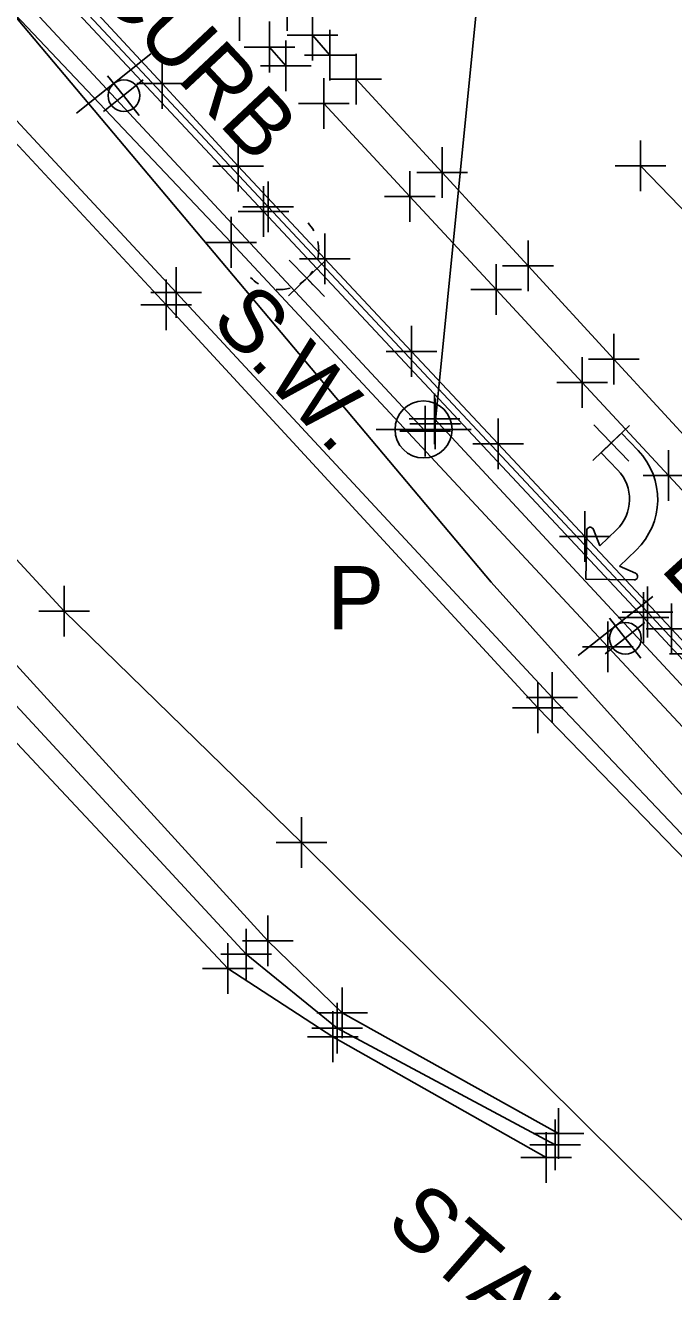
# Model space of a CAD drawing. Extents: x 0 to 1944463, y 0 to 420651.
# Drawn here: x 1943264.8 to 1943315.9, y 417235.5 to 417335.4 of the extents above; entities that cross this region are included whole.
import ezdxf

# ---------------------------------------------------------------- set-up
doc = ezdxf.new("R2010")
doc.units = 0
for name, color, linetype in [('SUR - DRG - Pipes and Culverts', 7, 'Continuous'), ('SUR - DRG - Pipes and Culverts - Points - Locators', 7, 'Continuous'), ('SUR - DTM - Breaklines', 7, 'Continuous'), ('SUR - DTM - Breaklines - Points - Locators', 7, 'Continuous'), ('SUR - NON-TRAN - Features Text', 7, 'Continuous'), ('SUR - TR-CTRL - Pavement Marking', 7, 'Continuous'), ('SUR - TR-CTRL - Pavement Marking - Points - Locators', 7, 'Continuous'), ('SUR - TR-CTRL - Signs and Devices', 7, 'Continuous'), ('SUR - TR-CTRL - Signs and Devices - Points - Locators', 7, 'Continuous'), ('SUR - TRAN - Features', 7, 'Continuous'), ('SUR - TRAN - Features - Points - Locators', 7, 'Continuous'), ('SUR - TRAN - Features Text', 7, 'Continuous'), ('SUR - UTL - Fiber Optic Cable (Underground)', 7, 'Continuous'), ('SUR - UTL - Overhead Wire Crossings', 7, 'Continuous'), ('SUR - UTL - Overhead Wire Crossings - Points - Locators', 7, 'Continuous'), ('SUR - UTL - Poles and Miscellaneous', 7, 'Continuous'), ('SUR - UTL - Poles and Miscellaneous - Points - Locators', 7, 'Continuous'), ('SUR - UTL - Poles and Miscellaneous Text', 7, 'Continuous')]:
    doc.layers.add(name, color=color, linetype=linetype)

msp = doc.modelspace()

# ---------------------------------------------------------------- linework, layer by layer
at = {"layer": 'SUR - DRG - Pipes and Culverts'}
for points in [[(1943306.855, 417247.978), (1943289.784, 417257.5), (1943283.915, 417263.16), (1943254.781, 417295.058), (1943224.294, 417329.482), (1943197.051, 417363.643)], [(1943305.862, 417246.088), (1943289.035, 417255.612), (1943280.758, 417260.995), (1943252.088, 417291.545), (1943220.601, 417326.41), (1943196.115, 417357.405)]]:
    msp.add_lwpolyline(points, dxfattribs=at)
at = {"layer": 'SUR - DRG - Pipes and Culverts - Points - Locators'}
for p, q in [((1943283.915, 417263.16), (1943283.915, 417265.16)), ((1943283.915, 417263.16), (1943281.915, 417263.16)), ((1943283.915, 417263.16), (1943285.915, 417263.16)), ((1943283.915, 417263.16), (1943283.915, 417261.16)), ((1943280.758, 417260.995), (1943280.758, 417262.995)), ((1943280.758, 417260.995), (1943278.758, 417260.995)), ((1943280.758, 417260.995), (1943282.758, 417260.995)), ((1943280.758, 417260.995), (1943280.758, 417258.995)), ((1943289.784, 417257.5), (1943289.784, 417259.5)), ((1943289.784, 417257.5), (1943287.784, 417257.5)), ((1943289.035, 417255.612), (1943289.035, 417257.612)), ((1943289.784, 417257.5), (1943291.784, 417257.5)), ((1943289.784, 417257.5), (1943289.784, 417255.5)), ((1943289.035, 417255.612), (1943287.035, 417255.612)), ((1943289.035, 417255.612), (1943291.035, 417255.612)), ((1943289.035, 417255.612), (1943289.035, 417253.612)), ((1943306.855, 417247.978), (1943306.855, 417249.978)), ((1943305.862, 417246.088), (1943305.862, 417248.088)), ((1943306.855, 417247.978), (1943304.855, 417247.978)), ((1943306.855, 417247.978), (1943308.855, 417247.978)), ((1943306.855, 417247.978), (1943306.855, 417245.978)), ((1943305.862, 417246.088), (1943303.862, 417246.088)), ((1943305.862, 417246.088), (1943307.862, 417246.088)), ((1943305.862, 417246.088), (1943305.862, 417244.088))]:
    msp.add_line(p, q, dxfattribs=at)
at = {"layer": 'SUR - DTM - Breaklines'}
for points in [[(1943201.925, 417419.272), (1943219.399, 417398.292), (1943235.519, 417375.7), (1943243.356, 417364.884), (1943258.929, 417346.985), (1943283.566, 417320.678), (1943313.562, 417288.656), (1943327.29, 417273.893), (1943334.736, 417264.52), (1943341.659, 417251.305), (1943344.574, 417242.404)], [(1943198.046, 417414.134), (1943214.079, 417390.624), (1943227.284, 417369.761), (1943234.656, 417359.391), (1943251.574, 417339.468), (1943275.895, 417313.326), (1943305.21, 417281.554), (1943319.493, 417266.816), (1943326.151, 417258.389), (1943333.033, 417247.541), (1943335.935, 417239.942), (1943336.414, 417217.406)], [(1943306.58, 417247.082), (1943289.389, 417256.286), (1943282.191, 417262.111), (1943253.295, 417293.316), (1943222.689, 417327.178), (1943196.285, 417361.224)], [(1943302.769, 417192.969), (1943316.957, 417194.129), (1943325.403, 417222.632), (1943318.173, 417239.593), (1943286.555, 417270.931), (1943267.833, 417289.169), (1943243.263, 417315.732), (1943226.41, 417332.649)]]:
    msp.add_lwpolyline(points, dxfattribs=at)
at = {"layer": 'SUR - DTM - Breaklines - Points - Locators'}
for p, q in [((1943283.566, 417320.678), (1943283.566, 417322.678)), ((1943283.566, 417320.678), (1943281.566, 417320.678)), ((1943283.566, 417320.678), (1943285.566, 417320.678)), ((1943283.566, 417320.678), (1943283.566, 417318.678)), ((1943275.895, 417313.326), (1943275.895, 417315.326)), ((1943275.895, 417313.326), (1943273.895, 417313.326)), ((1943275.895, 417313.326), (1943277.895, 417313.326)), ((1943275.895, 417313.326), (1943275.895, 417311.326)), ((1943267.833, 417289.169), (1943267.833, 417291.169)), ((1943313.562, 417288.656), (1943313.562, 417290.656)), ((1943267.833, 417289.169), (1943265.833, 417289.169)), ((1943267.833, 417289.169), (1943269.833, 417289.169)), ((1943267.833, 417289.169), (1943267.833, 417287.169)), ((1943313.562, 417288.656), (1943311.562, 417288.656)), ((1943313.562, 417288.656), (1943315.562, 417288.656)), ((1943313.562, 417288.656), (1943313.562, 417286.656)), ((1943305.21, 417281.554), (1943305.21, 417283.554)), ((1943305.21, 417281.554), (1943303.21, 417281.554)), ((1943305.21, 417281.554), (1943307.21, 417281.554)), ((1943305.21, 417281.554), (1943305.21, 417279.554)), ((1943286.555, 417270.931), (1943286.555, 417272.931)), ((1943286.555, 417270.931), (1943284.555, 417270.931)), ((1943286.555, 417270.931), (1943288.555, 417270.931)), ((1943286.555, 417270.931), (1943286.555, 417268.931)), ((1943282.191, 417262.111), (1943282.191, 417264.111)), ((1943282.191, 417262.111), (1943280.191, 417262.111)), ((1943282.191, 417262.111), (1943284.191, 417262.111)), ((1943282.191, 417262.111), (1943282.191, 417260.111)), ((1943289.389, 417256.286), (1943289.389, 417258.286)), ((1943289.389, 417256.286), (1943287.389, 417256.286)), ((1943289.389, 417256.286), (1943291.389, 417256.286)), ((1943289.389, 417256.286), (1943289.389, 417254.286)), ((1943306.58, 417247.082), (1943306.58, 417249.082)), ((1943306.58, 417247.082), (1943304.58, 417247.082)), ((1943306.58, 417247.082), (1943308.58, 417247.082)), ((1943306.58, 417247.082), (1943306.58, 417245.082))]:
    msp.add_line(p, q, dxfattribs=at)
at = {"layer": 'SUR - TR-CTRL - Pavement Marking'}
for p, q in [((1943310.207, 417301.657), (1943311.809, 417303.198)), ((1943310.207, 417301.657), (1943311.809, 417303.198)), ((1943311.809, 417303.198), (1943313.121, 417301.834)), ((1943311.809, 417303.198), (1943313.121, 417301.834)), ((1943311.008, 417302.427), (1943311.008, 417302.427)), ((1943310.207, 417301.657), (1943311.519, 417300.293)), ((1943310.207, 417301.657), (1943311.519, 417300.293)), ((1943308.995, 417291.698), (1943309.069, 417295.511)), ((1943308.995, 417291.698), (1943309.069, 417295.511)), ((1943310.112, 417294.314), (1943309.605, 417295.606)), ((1943310.112, 417294.314), (1943309.605, 417295.606)), ((1943311.428, 417295.58), (1943310.112, 417294.314)), ((1943311.428, 417295.58), (1943310.112, 417294.314)), ((1943312.969, 417293.978), (1943311.652, 417292.712)), ((1943312.969, 417293.978), (1943311.652, 417292.712)), ((1943311.652, 417292.712), (1943312.925, 417292.156)), ((1943311.652, 417292.712), (1943312.925, 417292.156)), ((1943308.995, 417291.698), (1943312.808, 417291.624)), ((1943308.995, 417291.698), (1943312.808, 417291.624))]:
    msp.add_line(p, q, dxfattribs=at)
for points in [[(1943268.798, 417338.12), (1943275.572, 417330.765), (1943281.577, 417324.245), (1943288.415, 417316.949), (1943295.254, 417309.653), (1943302.092, 417302.356), (1943308.93, 417295.06), (1943315.768, 417287.763), (1943317.602, 417285.807), (1943324.319, 417278.398), (1943331.036, 417270.99), (1943333.702, 417268.05), (1943337.073, 417264.332), (1943339.809, 417260.214)], [(1943287.426, 417334.58), (1943288.807, 417333.008)], [(1943284.029, 417333.651), (1943285.324, 417332.164)], [(1943290.889, 417331.107), (1943297.664, 417323.752), (1943304.439, 417316.397), (1943311.214, 417309.042), (1943317.989, 417301.686), (1943320.289, 417299.189), (1943327.064, 417291.834), (1943333.839, 417284.479), (1943340.614, 417277.123), (1943347.389, 417269.768), (1943354.164, 417262.413), (1943358.443, 417257.768)], [(1943313.304, 417324.282), (1943320.265, 417317.103), (1943320.521, 417316.838)]]:
    msp.add_lwpolyline(points, dxfattribs=at)
for centre, radius, start, end in [((1943309.117, 417297.982), 5.556, 313.89003, 43.89003), ((1943309.117, 417297.982), 5.556, 313.89003, 43.89003), ((1943309.117, 417297.982), 3.333, 313.89003, 43.89003), ((1943309.117, 417297.982), 3.333, 313.89003, 43.89003), ((1943309.347, 417295.505), 0.278, 21.39686, 178.89003), ((1943309.347, 417295.505), 0.278, 21.39686, 178.89003), ((1943312.814, 417291.902), 0.278, 268.89003, 66.33829), ((1943312.814, 417291.902), 0.278, 268.89003, 66.33829)]:
    msp.add_arc(centre, radius, start, end, dxfattribs=at)
at = {"layer": 'SUR - TR-CTRL - Pavement Marking - Points - Locators'}
for p, q in [((1943281.667, 417336.128), (1943281.667, 417334.128)), ((1943285.426, 417336.915), (1943285.426, 417334.915)), ((1943287.426, 417334.58), (1943287.426, 417336.58)), ((1943284.029, 417333.651), (1943284.029, 417335.651)), ((1943288.807, 417333.008), (1943288.807, 417335.008)), ((1943285.324, 417332.164), (1943285.324, 417334.164)), ((1943287.426, 417334.58), (1943285.426, 417334.58)), ((1943287.426, 417334.58), (1943289.426, 417334.58)), ((1943287.426, 417334.58), (1943287.426, 417332.58)), ((1943284.029, 417333.651), (1943282.029, 417333.651)), ((1943284.029, 417333.651), (1943286.029, 417333.651)), ((1943284.029, 417333.651), (1943284.029, 417331.651)), ((1943288.807, 417333.008), (1943286.807, 417333.008)), ((1943288.807, 417333.008), (1943290.807, 417333.008)), ((1943288.807, 417333.008), (1943288.807, 417331.008)), ((1943275.572, 417330.765), (1943275.572, 417332.765)), ((1943285.324, 417332.164), (1943283.324, 417332.164)), ((1943285.324, 417332.164), (1943287.324, 417332.164)), ((1943285.324, 417332.164), (1943285.324, 417330.164)), ((1943275.572, 417330.765), (1943273.572, 417330.765)), ((1943275.572, 417330.765), (1943277.572, 417330.765)), ((1943275.572, 417330.765), (1943275.572, 417328.765)), ((1943281.577, 417324.245), (1943281.577, 417326.245)), ((1943313.304, 417324.282), (1943313.304, 417326.282)), ((1943281.577, 417324.245), (1943279.577, 417324.245)), ((1943281.577, 417324.245), (1943283.577, 417324.245)), ((1943281.577, 417324.245), (1943281.577, 417322.245)), ((1943313.304, 417324.282), (1943311.304, 417324.282)), ((1943313.304, 417324.282), (1943315.304, 417324.282)), ((1943313.304, 417324.282), (1943313.304, 417322.282)), ((1943288.415, 417316.949), (1943288.415, 417318.949)), ((1943288.415, 417316.949), (1943286.415, 417316.949)), ((1943288.415, 417316.949), (1943290.415, 417316.949)), ((1943288.415, 417316.949), (1943288.415, 417314.949)), ((1943295.254, 417309.653), (1943295.254, 417311.653)), ((1943295.254, 417309.653), (1943293.254, 417309.653)), ((1943295.254, 417309.653), (1943297.254, 417309.653)), ((1943295.254, 417309.653), (1943295.254, 417307.653)), ((1943302.092, 417302.356), (1943302.092, 417304.356)), ((1943311.008, 417302.427), (1943309.622, 417303.869)), ((1943311.008, 417302.427), (1943312.45, 417303.814)), ((1943302.092, 417302.356), (1943300.092, 417302.356)), ((1943302.092, 417302.356), (1943304.092, 417302.356)), ((1943302.092, 417302.356), (1943302.092, 417300.356)), ((1943311.008, 417302.427), (1943309.567, 417301.041)), ((1943311.008, 417302.427), (1943312.395, 417300.986)), ((1943308.93, 417295.06), (1943308.93, 417297.06)), ((1943308.93, 417295.06), (1943306.93, 417295.06)), ((1943308.93, 417295.06), (1943310.93, 417295.06)), ((1943308.93, 417295.06), (1943308.93, 417293.06)), ((1943315.768, 417287.763), (1943315.768, 417289.763)), ((1943315.768, 417287.763), (1943313.768, 417287.763)), ((1943315.768, 417287.763), (1943317.768, 417287.763)), ((1943315.768, 417287.763), (1943315.768, 417285.763)), ((1943317.602, 417285.807), (1943315.602, 417285.807))]:
    msp.add_line(p, q, dxfattribs=at)
at = {"layer": 'SUR - TR-CTRL - Signs and Devices'}
for p, q in [((1943268.822, 417328.442), (1943274.685, 417333.119)), ((1943308.395, 417285.677), (1943314.28, 417290.326))]:
    msp.add_line(p, q, dxfattribs=at)
for centre in [(1943272.55, 417329.817), (1943312.129, 417287.034)]:
    msp.add_circle(centre, 1.25, dxfattribs=at)
at = {"layer": 'SUR - TR-CTRL - Signs and Devices - Points - Locators'}
for p, q in [((1943272.517, 417329.823), (1943271.27, 417331.387)), ((1943272.517, 417329.823), (1943274.081, 417331.07)), ((1943272.517, 417329.823), (1943270.954, 417328.576)), ((1943272.517, 417329.823), (1943273.765, 417328.26)), ((1943312.097, 417287.041), (1943310.857, 417288.61)), ((1943312.097, 417287.041), (1943313.666, 417288.281)), ((1943312.097, 417287.041), (1943310.527, 417285.801)), ((1943312.097, 417287.041), (1943313.337, 417285.472))]:
    msp.add_line(p, q, dxfattribs=at)
at = {"layer": 'SUR - TRAN - Features'}
for p, q in [((1943290.889, 417331.107), (1943290.889, 417333.107)), ((1943288.321, 417329.197), (1943288.321, 417331.197)), ((1943290.889, 417331.107), (1943288.889, 417331.107)), ((1943290.889, 417331.107), (1943292.889, 417331.107)), ((1943290.889, 417331.107), (1943290.889, 417329.107)), ((1943288.321, 417329.197), (1943286.321, 417329.197)), ((1943288.321, 417329.197), (1943290.321, 417329.197)), ((1943288.321, 417329.197), (1943288.321, 417327.197)), ((1943297.664, 417323.752), (1943297.664, 417325.752)), ((1943295.122, 417321.866), (1943295.122, 417323.866)), ((1943297.664, 417323.752), (1943295.664, 417323.752)), ((1943297.664, 417323.752), (1943299.664, 417323.752)), ((1943297.664, 417323.752), (1943297.664, 417321.752)), ((1943295.122, 417321.866), (1943293.122, 417321.866)), ((1943295.122, 417321.866), (1943297.122, 417321.866)), ((1943295.122, 417321.866), (1943295.122, 417319.866)), ((1943304.439, 417316.397), (1943304.439, 417318.397)), ((1943301.923, 417314.535), (1943301.923, 417316.535)), ((1943304.439, 417316.397), (1943302.439, 417316.397)), ((1943304.439, 417316.397), (1943306.439, 417316.397)), ((1943304.439, 417316.397), (1943304.439, 417314.397)), ((1943301.923, 417314.535), (1943299.923, 417314.535)), ((1943301.923, 417314.535), (1943303.923, 417314.535)), ((1943301.923, 417314.535), (1943301.923, 417312.535)), ((1943311.214, 417309.042), (1943311.214, 417311.042)), ((1943308.724, 417307.204), (1943308.724, 417309.204)), ((1943311.214, 417309.042), (1943309.214, 417309.042)), ((1943311.214, 417309.042), (1943313.214, 417309.042)), ((1943311.214, 417309.042), (1943311.214, 417307.042)), ((1943308.724, 417307.204), (1943306.724, 417307.204)), ((1943308.724, 417307.204), (1943310.724, 417307.204)), ((1943308.724, 417307.204), (1943308.724, 417305.204)), ((1943315.525, 417299.873), (1943315.525, 417301.873)), ((1943315.525, 417299.873), (1943313.525, 417299.873)), ((1943315.525, 417299.873), (1943317.525, 417299.873)), ((1943315.525, 417299.873), (1943315.525, 417297.873))]:
    msp.add_line(p, q, dxfattribs=at)
for points in [[(1943197.184, 417425.565), (1943202.015, 417420.067), (1943219.808, 417398.653), (1943235.891, 417376.011), (1943243.908, 417365.01), (1943259.423, 417347.224), (1943283.941, 417321.057), (1943313.88, 417289.098), (1943327.653, 417274.25), (1943335.225, 417264.751), (1943342.123, 417251.422), (1943345.054, 417242.562)], [(1943195.097, 417419.012), (1943198.722, 417414.702), (1943214.442, 417392.884), (1943228.699, 417370.699), (1943235.53, 417360.844), (1943252.431, 417340.382), (1943276.667, 417314.283), (1943306.333, 417282.353), (1943320.414, 417267.545), (1943327.507, 417259.182), (1943334.722, 417247.787), (1943337.989, 417240.637)], [(1943258.845, 417346.781), (1943256.359, 417344.242), (1943281.019, 417318.249), (1943310.741, 417286.356), (1943324.425, 417271.702), (1943327.194, 417273.746)], [(1943288.321, 417329.197), (1943295.122, 417321.866), (1943301.923, 417314.535), (1943308.724, 417307.204), (1943315.525, 417299.873), (1943320.194, 417294.84), (1943326.954, 417287.471), (1943333.714, 417280.102), (1943340.474, 417272.733), (1943347.234, 417265.364), (1943353.994, 417257.995), (1943356.391, 417255.381)]]:
    msp.add_lwpolyline(points, dxfattribs=at)
at = {"layer": 'SUR - TRAN - Features - Points - Locators'}
for p, q in [((1943283.941, 417321.057), (1943283.941, 417323.057)), ((1943283.941, 417321.057), (1943281.941, 417321.057)), ((1943283.941, 417321.057), (1943285.941, 417321.057)), ((1943283.941, 417321.057), (1943283.941, 417319.057)), ((1943281.019, 417318.249), (1943281.019, 417320.249)), ((1943281.019, 417318.249), (1943279.019, 417318.249)), ((1943281.019, 417318.249), (1943283.019, 417318.249)), ((1943281.019, 417318.249), (1943281.019, 417316.249)), ((1943276.667, 417314.283), (1943276.667, 417316.283)), ((1943276.667, 417314.283), (1943274.667, 417314.283)), ((1943276.667, 417314.283), (1943278.667, 417314.283)), ((1943276.667, 417314.283), (1943276.667, 417312.283)), ((1943313.88, 417289.098), (1943313.88, 417291.098)), ((1943313.88, 417289.098), (1943311.88, 417289.098)), ((1943313.88, 417289.098), (1943315.88, 417289.098)), ((1943313.88, 417289.098), (1943313.88, 417287.098)), ((1943310.741, 417286.356), (1943310.741, 417288.356)), ((1943310.741, 417286.356), (1943308.741, 417286.356)), ((1943310.741, 417286.356), (1943312.741, 417286.356)), ((1943310.741, 417286.356), (1943310.741, 417284.356)), ((1943306.333, 417282.353), (1943306.333, 417284.353)), ((1943306.333, 417282.353), (1943304.333, 417282.353)), ((1943306.333, 417282.353), (1943308.333, 417282.353)), ((1943306.333, 417282.353), (1943306.333, 417280.353))]:
    msp.add_line(p, q, dxfattribs=at)
at = {"layer": 'SUR - UTL - Fiber Optic Cable (Underground)'}
msp.add_lwpolyline([(1943675.935, 416874.811), (1943301.532, 417291.453), (1943229.017, 417377.593), (1943204.769, 417412.08), (1943079.474, 417545.559), (1943001.447, 417611.824), (1942943.851, 417666.04), (1942875.969, 417717.873), (1942785.445, 417773.544), (1942671.047, 417813.855), (1942647.996, 417834.422), (1942364.461, 417940.541)], dxfattribs=at)
at = {"layer": 'SUR - UTL - Overhead Wire Crossings'}
for points in [[(1943297.11, 417303.94), (1943309.92, 417432.31)], [(1943200.06, 417406.7), (1943296.33, 417303.35)], [(1943297.06, 417304.33), (1943429.93, 417161.294)]]:
    msp.add_lwpolyline(points, dxfattribs=at)
at = {"layer": 'SUR - UTL - Overhead Wire Crossings - Points - Locators'}
for p, q in [((1943297.06, 417304.33), (1943297.06, 417306.33)), ((1943296.33, 417303.35), (1943296.33, 417305.35)), ((1943297.11, 417303.94), (1943297.11, 417305.94)), ((1943297.06, 417304.33), (1943295.06, 417304.33)), ((1943297.06, 417304.33), (1943299.06, 417304.33)), ((1943297.06, 417304.33), (1943297.06, 417302.33)), ((1943296.33, 417303.35), (1943294.33, 417303.35)), ((1943297.11, 417303.94), (1943295.11, 417303.94)), ((1943296.33, 417303.35), (1943298.33, 417303.35)), ((1943296.33, 417303.35), (1943296.33, 417301.35)), ((1943297.11, 417303.94), (1943299.11, 417303.94)), ((1943297.11, 417303.94), (1943297.11, 417301.94))]:
    msp.add_line(p, q, dxfattribs=at)
at = {"layer": 'SUR - UTL - Poles and Miscellaneous'}
for p, q in [((1943287.47, 417314.907), (1943286.984, 417315.411)), ((1943296.196, 417303.495), (1943292.446, 417303.495)), ((1943296.196, 417303.495), (1943299.946, 417303.495))]:
    msp.add_line(p, q, dxfattribs=at)
msp.add_circle((1943296.196, 417303.495), 2.25, dxfattribs=at)
for start, end in [(29.14146, 43.03088), (347.51767, 12.28771), (301.47586, 327.99117), (223.95493, 238.5758), (265.8328, 286.17531)]:
    msp.add_arc((1943284.797, 417317.643), 3.125, start, end, dxfattribs=at)
at = {"layer": 'SUR - UTL - Poles and Miscellaneous - Points - Locators'}
for q in [(1943285.596, 417316.851), (1943288.424, 417316.799), (1943285.544, 417314.023), (1943288.372, 417313.971)]:
    msp.add_line((1943286.984, 417315.411), q, dxfattribs=at)

# ---------------------------------------------------------------- texts
at = {"layer": 'SUR - NON-TRAN - Features Text'}
msp.add_text('STAIRS', height=5, rotation=318.74395, dxfattribs=at).set_placement((1943293.052, 417240.731))
at = {"layer": 'SUR - TRAN - Features Text'}
for s, height, rotation, p in [('CURB', 5, 313.13649, (1943270.055, 417338.151)), ('S.W.', 5, 312.98127, (1943279.294, 417311.997)), ('BIKE PATH (ASP)', 4.99999, 312.28203, (1943314.791, 417292.486))]:
    msp.add_text(s, height=height, rotation=rotation, dxfattribs=at).set_placement(p)
at = {"layer": 'SUR - UTL - Poles and Miscellaneous Text'}
msp.add_text('P', height=5, dxfattribs=at).set_placement((1943288.616, 417287.72))

doc.saveas('drawing.dxf')
